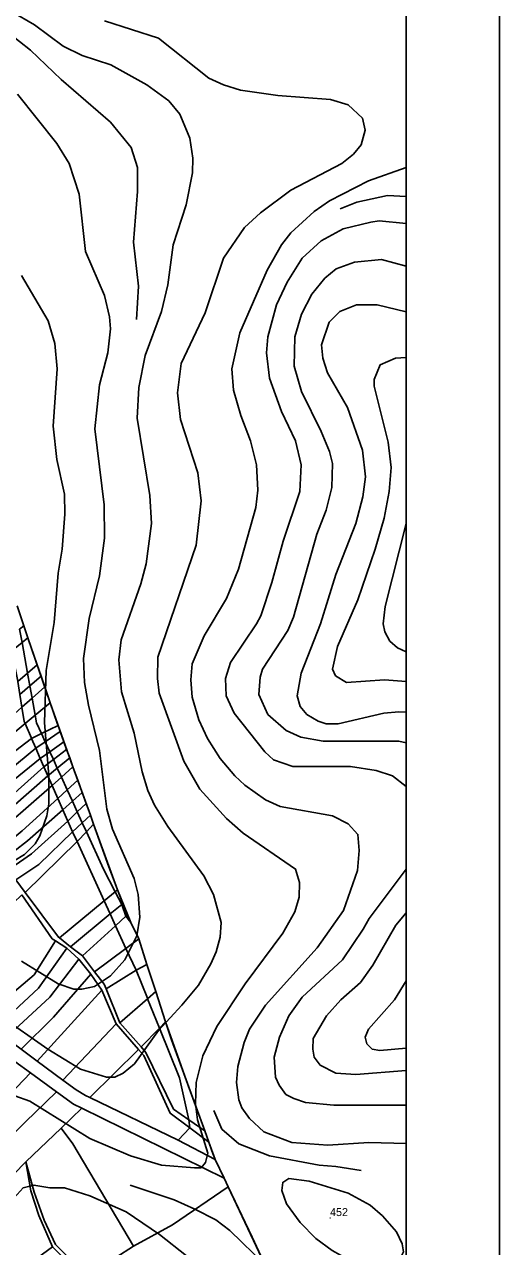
# Model space of a CAD drawing. Extents: x -510989 to -501240, y -1184665 to -1176089.
# Drawn here: x -508375 to -508019, y -1180002 to -1179086 of the extents above; entities that cross this region are included whole.
import ezdxf

# ---------------------------------------------------------------- set-up
doc = ezdxf.new("R2010")
doc.units = 0
for name, color, linetype in [('lesni_pozemek', 7, 'Continuous'), ('ostatni_plocha_x_ostatni_komunikace', 7, 'Continuous'), ('ostatni_plocha_x_silnice', 7, 'Continuous'), ('popis', 7, 'Continuous'), ('rozpiska', 7, 'Continuous'), ('vodni_plocha_x_vodni_tok_v_koryt_prir_n_upr', 7, 'Continuous'), ('vrstevnice_01', 7, 'Continuous'), ('vrstevnice_02', 7, 'Continuous'), ('vrstevnice_03', 7, 'Continuous'), ('vrstevnice_05', 7, 'Continuous')]:
    doc.layers.add(name, color=color, linetype=linetype)

msp = doc.modelspace()

# ---------------------------------------------------------------- linework, layer by layer
at = {"layer": 'lesni_pozemek'}
for points in [[(-508375.28, -1179536.65), (-508372.26, -1179545.49), (-508376.69, -1179549.11), (-508378.49, -1179539.21)], [(-508372.26, -1179545.49), (-508365.32, -1179565.8), (-508372.54, -1179571.99), (-508376.69, -1179549.11)], [(-508365.32, -1179565.8), (-508362.35, -1179574.47), (-508370.78, -1179581.68), (-508372.54, -1179571.99)], [(-508362.35, -1179574.47), (-508359.69, -1179582.26), (-508369.13, -1179590.78), (-508370.78, -1179581.68)], [(-508359.69, -1179582.26), (-508355.58, -1179594.3), (-508366.8, -1179603.6), (-508369.13, -1179590.78)], [(-508355.58, -1179594.3), (-508350.34, -1179609.63), (-508349.73, -1179611.32), (-508362.08, -1179617.47), (-508365.74, -1179609.44), (-508366.8, -1179603.6)], [(-508375.12, -1179608.36), (-508374.43, -1179609.93), (-508432.44, -1179658), (-508439.11, -1179650.99), (-508407.25, -1179625.19), (-508376.81, -1179597.71)], [(-508369.63, -1179620.89), (-508369.51, -1179621.18), (-508426.38, -1179664.36), (-508432.44, -1179658), (-508374.43, -1179609.93)], [(-508348.08, -1179615.91), (-508359.29, -1179623.59), (-508362.08, -1179617.47), (-508349.73, -1179611.32)], [(-508366.34, -1179628.42), (-508399.73, -1179655.76), (-508422.61, -1179671.19), (-508426.38, -1179664.36), (-508369.51, -1179621.18)], [(-508345.34, -1179623.5), (-508355.9, -1179631.02), (-508359.29, -1179623.59), (-508348.08, -1179615.91)], [(-508343.27, -1179629.27), (-508353.2, -1179636.93), (-508355.9, -1179631.02), (-508345.34, -1179623.5)], [(-508362.99, -1179636.07), (-508397.99, -1179664.33), (-508419.67, -1179678.67), (-508422.61, -1179671.19), (-508399.73, -1179655.76), (-508366.34, -1179628.42)], [(-508340.96, -1179635.68), (-508350.27, -1179643.36), (-508353.2, -1179636.93), (-508343.27, -1179629.27)], [(-508360.24, -1179642.36), (-508394.41, -1179672.71), (-508414.98, -1179684.95), (-508419.35, -1179679.5), (-508419.67, -1179678.67), (-508397.99, -1179664.33), (-508362.99, -1179636.07)], [(-508357.27, -1179649.13), (-508383.88, -1179672.33), (-508409.65, -1179691.6), (-508414.98, -1179684.95), (-508394.41, -1179672.71), (-508360.24, -1179642.36)], [(-508338.55, -1179642.35), (-508347.16, -1179650.18), (-508350.27, -1179643.36), (-508340.96, -1179635.68)], [(-508338.55, -1179642.35), (-508334.94, -1179652.39), (-508342.85, -1179659.62), (-508347.16, -1179650.18)], [(-508354.06, -1179656.46), (-508403.49, -1179699.29), (-508409.65, -1179691.6), (-508383.88, -1179672.33), (-508357.27, -1179649.13)], [(-508349.87, -1179666.04), (-508376.53, -1179690.45), (-508397.66, -1179707.63), (-508403.49, -1179699.29), (-508354.06, -1179656.46)], [(-508334.94, -1179652.39), (-508331.63, -1179661.58), (-508338.93, -1179668.21), (-508342.85, -1179659.62)], [(-508346.08, -1179674.71), (-508372.64, -1179697.96), (-508393.3, -1179713.87), (-508397.66, -1179707.63), (-508376.53, -1179690.45), (-508349.87, -1179666.04)], [(-508331.63, -1179661.58), (-508328.66, -1179669.81), (-508335.3, -1179676.16), (-508338.93, -1179668.21)], [(-508328.66, -1179669.81), (-508325.46, -1179678.69), (-508331.57, -1179684.33), (-508335.3, -1179676.16)], [(-508342.64, -1179682.55), (-508342.44, -1179683), (-508369.66, -1179707.55), (-508387.54, -1179720.12), (-508393.3, -1179713.87), (-508372.64, -1179697.96), (-508346.08, -1179674.71)], [(-508325.46, -1179678.69), (-508323.04, -1179685.4), (-508328.5, -1179691.06), (-508331.57, -1179684.33)], [(-508338.81, -1179691), (-508364.15, -1179715.53), (-508381.36, -1179727), (-508381.97, -1179726.17), (-508387.54, -1179720.12), (-508369.66, -1179707.55), (-508342.44, -1179683)], [(-508323.04, -1179685.4), (-508311.57, -1179717.24), (-508307.73, -1179727.9), (-508305.17, -1179734.59), (-508306.93, -1179736.06), (-508315.72, -1179719.07), (-508328.5, -1179691.06)], [(-508335.49, -1179698.31), (-508374.33, -1179736.49), (-508381.36, -1179727), (-508364.15, -1179715.53), (-508338.81, -1179691)], [(-508335.49, -1179698.31), (-508315.24, -1179742.94), (-508348.72, -1179770.69), (-508349.45, -1179770.12), (-508374.33, -1179736.49)], [(-508306.93, -1179736.06), (-508305.17, -1179734.59), (-508301.26, -1179744.83), (-508302.06, -1179745.49)], [(-508376.78, -1179738.27), (-508354.07, -1179771.31), (-508351.52, -1179772.94), (-508367.55, -1179798.25), (-508407.24, -1179831.91), (-508438.55, -1179808.7), (-508445.83, -1179804.3)], [(-508310.75, -1179752.69), (-508340.36, -1179777.21), (-508348.72, -1179770.69), (-508315.24, -1179742.94)], [(-508306.69, -1179761.51), (-508331.42, -1179784.18), (-508340.36, -1179777.21), (-508310.75, -1179752.69)], [(-508302.06, -1179745.49), (-508301.26, -1179744.83), (-508301.01, -1179745.49), (-508300.82, -1179745.98), (-508300.48, -1179746.87), (-508298.23, -1179752.78), (-508298.86, -1179754.33)], [(-508298.86, -1179754.33), (-508298.23, -1179752.78), (-508297.34, -1179754.61), (-508296.57, -1179756.18), (-508295.18, -1179759.04)], [(-508298.83, -1179778.58), (-508322.34, -1179796.08), (-508331.42, -1179784.18), (-508306.69, -1179761.51)], [(-508351.52, -1179772.94), (-508343.01, -1179778.39), (-508364.37, -1179808.2), (-508397.48, -1179839.14), (-508407.24, -1179831.91), (-508367.55, -1179798.25)], [(-508343.01, -1179778.39), (-508334.12, -1179786.6), (-508355.81, -1179815.14), (-508388.85, -1179845.53), (-508397.48, -1179839.14), (-508364.37, -1179808.2)], [(-508291.31, -1179794.91), (-508313.8, -1179808.92), (-508315.24, -1179805.39), (-508322.34, -1179796.08), (-508298.83, -1179778.58)], [(-508334.12, -1179786.6), (-508325.1, -1179797.79), (-508353.02, -1179830.13), (-508377.34, -1179854.07), (-508388.85, -1179845.53), (-508355.81, -1179815.14)], [(-508325.1, -1179797.79), (-508317.01, -1179809.73), (-508365.34, -1179862.96), (-508377.34, -1179854.07), (-508353.02, -1179830.13)], [(-508291.31, -1179794.91), (-508282.83, -1179815.88), (-508282.69, -1179816.22), (-508303.46, -1179834.36), (-508313.8, -1179808.92)], [(-508317.01, -1179809.73), (-508306.28, -1179834.94), (-508346.11, -1179877.21), (-508365.34, -1179862.96)], [(-508282.69, -1179816.22), (-508273.74, -1179838.34), (-508287.58, -1179852.38), (-508303.46, -1179834.36)], [(-508306.28, -1179834.94), (-508289.48, -1179854.27), (-508325.79, -1179890.38), (-508329.1, -1179888.78), (-508336.21, -1179884.55), (-508346.11, -1179877.21)], [(-508273.74, -1179838.34), (-508258.72, -1179875.46), (-508251.76, -1179906.97), (-508263.28, -1179899.04), (-508283.99, -1179856.46), (-508287.58, -1179852.38)], [(-508289.48, -1179854.27), (-508285.58, -1179858.75), (-508265.71, -1179902.1), (-508251.05, -1179913.07), (-508259.65, -1179922.4), (-508325.79, -1179890.38)], [(-508370.42, -1179871.92), (-508401.61, -1179904.42), (-508458.1, -1179958.48), (-508498.54, -1179988.71), (-508501.52, -1179976.96), (-508501.92, -1179965.5), (-508470.77, -1179943.05), (-508410.19, -1179889.28), (-508382.16, -1179863.41)], [(-508350.98, -1179886.01), (-508374.4, -1179908.75), (-508410.81, -1179945.25), (-508441.23, -1179972.85), (-508490.99, -1180012.47), (-508498.54, -1179988.71), (-508458.1, -1179958.48), (-508401.61, -1179904.42), (-508370.42, -1179871.92)], [(-508338.03, -1179895.39), (-508331.91, -1179898.4), (-508347.37, -1179913.24), (-508373.72, -1179938.52), (-508401.29, -1179966.61), (-508438.7, -1179998.77), (-508483.59, -1180035.75), (-508490.99, -1180012.47), (-508441.23, -1179972.85), (-508410.81, -1179945.25), (-508374.4, -1179908.75), (-508350.98, -1179886.01)], [(-508347.37, -1179913.24), (-508331.91, -1179898.4), (-508225.42, -1179950.88), (-508222.42, -1179957.19), (-508264.07, -1179985.88), (-508293.14, -1180001.85), (-508338.56, -1179924.99)], [(-508338.56, -1179924.99), (-508293.14, -1180001.85), (-508306.41, -1180010.22), (-508325.34, -1180026.8), (-508351.58, -1180000.65), (-508360.15, -1179982.23), (-508367.63, -1179961.39), (-508373.72, -1179938.52), (-508347.37, -1179913.24)], [(-508370.14, -1179960.34), (-508364.19, -1179978.89), (-508353.93, -1180002.31), (-508373.58, -1180016.68), (-508396.42, -1180036.4), (-508416.63, -1180051.92), (-508475.36, -1180090.66), (-508483.59, -1180035.75), (-508438.7, -1179998.77), (-508401.29, -1179966.61), (-508373.72, -1179938.52)], [(-508264.07, -1179985.88), (-508222.42, -1179957.19), (-508204.32, -1179995.16), (-508177.34, -1180053.09), (-508152.46, -1180106.83), (-508173.6, -1180123.17), (-508192.01, -1180134.69), (-508215.78, -1180151.38), (-508240.41, -1180170.53), (-508260.19, -1180138.45), (-508277.13, -1180118.72), (-508286.73, -1180111.41), (-508303.87, -1180065.86), (-508325.34, -1180026.8), (-508306.41, -1180010.22), (-508293.14, -1180001.85)]]:
    msp.add_lwpolyline(points, close=True, dxfattribs=at)
at = {"layer": 'ostatni_plocha_x_ostatni_komunikace'}
for points in [[(-508376.69, -1179549.11), (-508372.54, -1179571.99), (-508379.9, -1179578.29), (-508380.14, -1179576.77), (-508384.32, -1179555.34)], [(-508372.54, -1179571.99), (-508370.78, -1179581.68), (-508378.33, -1179588.14), (-508379.9, -1179578.29)], [(-508370.78, -1179581.68), (-508369.13, -1179590.78), (-508376.81, -1179597.71), (-508378.33, -1179588.14)], [(-508369.13, -1179590.78), (-508366.8, -1179603.6), (-508374.43, -1179609.93), (-508375.12, -1179608.36), (-508376.81, -1179597.71)], [(-508365.74, -1179609.44), (-508362.08, -1179617.47), (-508369.51, -1179621.18), (-508369.63, -1179620.89), (-508374.43, -1179609.93), (-508366.8, -1179603.6)], [(-508362.08, -1179617.47), (-508359.29, -1179623.59), (-508366.34, -1179628.42), (-508369.51, -1179621.18)], [(-508359.29, -1179623.59), (-508355.9, -1179631.02), (-508362.99, -1179636.07), (-508366.34, -1179628.42)], [(-508355.9, -1179631.02), (-508353.2, -1179636.93), (-508360.24, -1179642.36), (-508362.99, -1179636.07)], [(-508353.2, -1179636.93), (-508350.27, -1179643.36), (-508357.27, -1179649.13), (-508360.24, -1179642.36)], [(-508350.27, -1179643.36), (-508347.16, -1179650.18), (-508354.06, -1179656.46), (-508357.27, -1179649.13)], [(-508347.16, -1179650.18), (-508342.85, -1179659.62), (-508349.87, -1179666.04), (-508354.06, -1179656.46)], [(-508342.85, -1179659.62), (-508338.93, -1179668.21), (-508346.08, -1179674.71), (-508349.87, -1179666.04)], [(-508338.93, -1179668.21), (-508335.3, -1179676.16), (-508342.44, -1179683), (-508342.64, -1179682.55), (-508346.08, -1179674.71)], [(-508335.3, -1179676.16), (-508331.57, -1179684.33), (-508338.81, -1179691), (-508342.44, -1179683)], [(-508331.57, -1179684.33), (-508328.5, -1179691.06), (-508335.49, -1179698.31), (-508338.81, -1179691)], [(-508328.5, -1179691.06), (-508315.72, -1179719.07), (-508306.93, -1179736.06), (-508315.24, -1179742.94), (-508335.49, -1179698.31)], [(-508315.24, -1179742.94), (-508306.93, -1179736.06), (-508302.06, -1179745.49), (-508310.75, -1179752.69)], [(-508302.06, -1179745.49), (-508298.86, -1179754.33), (-508306.69, -1179761.51), (-508310.75, -1179752.69)], [(-508298.86, -1179754.33), (-508295.18, -1179759.04), (-508289.71, -1179770.24), (-508289.15, -1179771.38), (-508298.83, -1179778.58), (-508306.69, -1179761.51)], [(-508289.15, -1179771.38), (-508283.14, -1179790.49), (-508291.31, -1179794.91), (-508298.83, -1179778.58)], [(-508291.31, -1179794.91), (-508283.14, -1179790.49), (-508276.53, -1179810.83), (-508282.69, -1179816.22), (-508282.83, -1179815.88)], [(-508276.53, -1179810.83), (-508269.12, -1179833.65), (-508273.74, -1179838.34), (-508282.69, -1179816.22)], [(-508269.12, -1179833.65), (-508264.73, -1179847.18), (-508239.71, -1179915.27), (-508251.76, -1179906.97), (-508258.72, -1179875.46), (-508273.74, -1179838.34)], [(-508251.05, -1179913.07), (-508251.76, -1179906.97), (-508239.71, -1179915.27), (-508236.74, -1179923.78)], [(-508259.65, -1179922.4), (-508251.05, -1179913.07), (-508236.74, -1179923.78), (-508234.45, -1179930.36), (-508231.98, -1179936.72)]]:
    msp.add_lwpolyline(points, close=True, dxfattribs=at)
msp.add_lwpolyline([(-508381.36, -1179727), (-508374.33, -1179736.49), (-508349.45, -1179770.12), (-508348.72, -1179770.69), (-508340.36, -1179777.21), (-508331.42, -1179784.18), (-508322.34, -1179796.08), (-508315.24, -1179805.39), (-508313.8, -1179808.92), (-508303.46, -1179834.36), (-508287.58, -1179852.38), (-508283.99, -1179856.46), (-508263.28, -1179899.04), (-508251.76, -1179906.97), (-508251.05, -1179913.07), (-508265.71, -1179902.1), (-508285.58, -1179858.75), (-508289.48, -1179854.27), (-508306.28, -1179834.94), (-508317.01, -1179809.73), (-508325.1, -1179797.79), (-508334.12, -1179786.6), (-508343.01, -1179778.39), (-508351.52, -1179772.94), (-508354.07, -1179771.31), (-508376.78, -1179738.27)], dxfattribs=at)
at = {"layer": 'ostatni_plocha_x_silnice'}
msp.add_lwpolyline([(-508377.34, -1179854.07), (-508365.34, -1179862.96), (-508346.11, -1179877.21), (-508336.21, -1179884.55), (-508329.1, -1179888.78), (-508325.79, -1179890.38), (-508259.65, -1179922.4), (-508231.98, -1179936.72), (-508225.42, -1179950.88), (-508331.91, -1179898.4), (-508338.03, -1179895.39), (-508350.98, -1179886.01), (-508370.42, -1179871.92), (-508382.16, -1179863.41)], dxfattribs=at)
at = {"layer": 'popis'}
msp.add_lwpolyline([(-508380.42, -1179521.72), (-508372.26, -1179545.49), (-508355.58, -1179594.3), (-508338.55, -1179642.35), (-508325.46, -1179678.69), (-508323.04, -1179685.4), (-508305.17, -1179734.59), (-508295.18, -1179759.04), (-508289.15, -1179771.38), (-508283.14, -1179790.49), (-508276.53, -1179810.83), (-508269.12, -1179833.65), (-508252.22, -1179881.23), (-508239.71, -1179915.27), (-508236.74, -1179923.78), (-508231.98, -1179936.72), (-508225.42, -1179950.88), (-508222.42, -1179957.19), (-508190.83, -1180024.12)], dxfattribs=at)
at = {"layer": 'rozpiska'}
for points in [[(-508019.09, -1176098), (-508019.09, -1184498), (-510989.09, -1184498), (-510989.09, -1176098)], [(-508089.09, -1176168), (-508089.09, -1184428), (-510919.09, -1184428), (-510919.09, -1176168)]]:
    msp.add_lwpolyline(points, close=True, dxfattribs=at)
at = {"layer": 'vodni_plocha_x_vodni_tok_v_koryt_prir_n_upr'}
msp.add_lwpolyline([(-508370.14, -1179960.34), (-508373.72, -1179938.52), (-508367.63, -1179961.39), (-508360.15, -1179982.23), (-508351.58, -1180000.65), (-508325.34, -1180026.8), (-508303.87, -1180065.86), (-508286.73, -1180111.41), (-508277.13, -1180118.72), (-508260.19, -1180138.45), (-508240.41, -1180170.53), (-508241.39, -1180171.23), (-508243.46, -1180173.21), (-508260.33, -1180143.53), (-508277.13, -1180123.03), (-508288.99, -1180112.76), (-508305.92, -1180067.56), (-508326.79, -1180029.11), (-508353.93, -1180002.31), (-508364.19, -1179978.89)], close=True, dxfattribs=at)
at = {"layer": 'vrstevnice_01'}
for points in [[(-508382.19, -1179889), (-508370.91, -1179893), (-508326, -1179921), (-508295.41, -1179934), (-508272.31, -1179941), (-508247.5, -1179943), (-508242.59, -1179943), (-508239.19, -1179939), (-508237.59, -1179932), (-508245.31, -1179907), (-508246.69, -1179895), (-508246.19, -1179879), (-508241.19, -1179859), (-508230.91, -1179837), (-508209.59, -1179805), (-508181.31, -1179767), (-508172.31, -1179751), (-508169.19, -1179740), (-508169, -1179729), (-508172, -1179719), (-508211.09, -1179692), (-508223.5, -1179681), (-508243.59, -1179659), (-508255.59, -1179638), (-508273.91, -1179587), (-508275.19, -1179576), (-508274.91, -1179560), (-508246.31, -1179476), (-508242.59, -1179443), (-508244.91, -1179422), (-508257.91, -1179382), (-508260.19, -1179362), (-508257.5, -1179340), (-508239.5, -1179302), (-508225.81, -1179261), (-508210.09, -1179238), (-508198.09, -1179227), (-508175.31, -1179210), (-508137.31, -1179190), (-508128.5, -1179183), (-508122.69, -1179176), (-508119.59, -1179165), (-508121.59, -1179156), (-508132.5, -1179146), (-508145.69, -1179142), (-508185, -1179139), (-508213.09, -1179135), (-508225.91, -1179131), (-508236.91, -1179126), (-508274.41, -1179096), (-508314.91, -1179083)], [(-508377, -1179788), (-508349.69, -1179805), (-508337.81, -1179809), (-508331.81, -1179809), (-508322.5, -1179807), (-508310.5, -1179799), (-508299.81, -1179787), (-508290.69, -1179769), (-508288.41, -1179755), (-508289.81, -1179738), (-508292.81, -1179726), (-508309, -1179689), (-508313.19, -1179674), (-508318.69, -1179630), (-508326.81, -1179596), (-508329.81, -1179579), (-508330.59, -1179561), (-508326.41, -1179531), (-508318.59, -1179499), (-508315, -1179471), (-508315.09, -1179446), (-508322.09, -1179389), (-508318.59, -1179356), (-508312.5, -1179332), (-508310.31, -1179314), (-508311.09, -1179305), (-508315, -1179289), (-508329.19, -1179256), (-508333.81, -1179213), (-508341.5, -1179190), (-508350.5, -1179175), (-508380.09, -1179138)], [(-508089.09, -1179234.93), (-508109.31, -1179233), (-508115.41, -1179234), (-508136.19, -1179239), (-508152.59, -1179248), (-508166.81, -1179261), (-508178.19, -1179279), (-508186.19, -1179296), (-508192.69, -1179320), (-508193.69, -1179332), (-508191.41, -1179351), (-508182.41, -1179376), (-508171.91, -1179398), (-508167.59, -1179416), (-508168.69, -1179436), (-508181.09, -1179473), (-508189.5, -1179504), (-508197.81, -1179529), (-508201.19, -1179535), (-508220.5, -1179564), (-508224.31, -1179576), (-508223.81, -1179589), (-508217.91, -1179602), (-508194.81, -1179631), (-508188.41, -1179637), (-508173.91, -1179642), (-508130.81, -1179642), (-508111.5, -1179645), (-508099.19, -1179649), (-508089.09, -1179657.17)], [(-508089.09, -1179601.33), (-508094.5, -1179601), (-508105.69, -1179602), (-508139.81, -1179610), (-508148.91, -1179610), (-508154.91, -1179608), (-508163.31, -1179603), (-508168.41, -1179597), (-508170.59, -1179589), (-508167.69, -1179572), (-508153.19, -1179535), (-508141.59, -1179498), (-508126.81, -1179460), (-508121.5, -1179440), (-508119.41, -1179425), (-508121.59, -1179405), (-508133, -1179373), (-508148, -1179347), (-508151.41, -1179336), (-508152.31, -1179326), (-508146.69, -1179309), (-508138.69, -1179301), (-508126.09, -1179296), (-508110.81, -1179296), (-508089.09, -1179301.15)], [(-508089.09, -1179459.98), (-508089.09, -1179460), (-508104.81, -1179522), (-508106.31, -1179535), (-508105, -1179541), (-508101.31, -1179548), (-508095.59, -1179553), (-508089.09, -1179556.16)], [(-508089.09, -1179719.04), (-508116.81, -1179756), (-508121.31, -1179764), (-508136.81, -1179787), (-508167, -1179815), (-508177, -1179829), (-508183.91, -1179845), (-508187.91, -1179860), (-508186.81, -1179875), (-508184.09, -1179881), (-508179, -1179888), (-508173.19, -1179891), (-508164.31, -1179894), (-508143.19, -1179896), (-508089.09, -1179896)], [(-508089.09, -1179853.25), (-508108.69, -1179855), (-508114.5, -1179854), (-508118.41, -1179850), (-508119.81, -1179845), (-508117.31, -1179839), (-508097.69, -1179817), (-508089.09, -1179802.78)], [(-508106.81, -1179979), (-508096.19, -1179991), (-508091.91, -1180000), (-508091.09, -1180006), (-508093, -1180010), (-508099.81, -1180016), (-508105, -1180017), (-508119.81, -1180016), (-508131.91, -1180012), (-508144.31, -1180005), (-508156.59, -1179996), (-508168.31, -1179984), (-508178.69, -1179970), (-508182.19, -1179960), (-508181.41, -1179954), (-508176.81, -1179951), (-508161.59, -1179953), (-508132.5, -1179962), (-508116, -1179971), (-508106.81, -1179979)]]:
    msp.add_lwpolyline(points, dxfattribs=at)
at = {"layer": 'vrstevnice_02'}
for points in [[(-508384.69, -1179076), (-508367.31, -1179086), (-508345.81, -1179102), (-508331.69, -1179109), (-508310.19, -1179116), (-508283.19, -1179131), (-508266.81, -1179143), (-508258.41, -1179153), (-508251, -1179171), (-508248.81, -1179186), (-508249.09, -1179197), (-508253.81, -1179221), (-508263.59, -1179251), (-508267.41, -1179281), (-508272.31, -1179301), (-508284.41, -1179334), (-508289.31, -1179358), (-508290.41, -1179381), (-508281, -1179439), (-508279.69, -1179460), (-508283.69, -1179490), (-508287.69, -1179505), (-508302.5, -1179547), (-508304.19, -1179562), (-508302.19, -1179586), (-508292.69, -1179617), (-508286.81, -1179646), (-508282.5, -1179660), (-508277.41, -1179671), (-508267.59, -1179687), (-508240.59, -1179724), (-508233.19, -1179738), (-508227.59, -1179759), (-508228.41, -1179770), (-508231.41, -1179781), (-508235.19, -1179790), (-508244.5, -1179806), (-508257, -1179821), (-508274.5, -1179840), (-508292.5, -1179865), (-508301, -1179872), (-508307.31, -1179875), (-508313.41, -1179875), (-508332.91, -1179869), (-508357.31, -1179854), (-508393.31, -1179829)], [(-508089.09, -1179924.71), (-508117.09, -1179924), (-508147.69, -1179926), (-508174.69, -1179924), (-508195.5, -1179916), (-508206.41, -1179906), (-508212, -1179898), (-508214.31, -1179892), (-508216.09, -1179879), (-508215.09, -1179867), (-508210.31, -1179849), (-508206.31, -1179839), (-508194.31, -1179821), (-508155.59, -1179778), (-508136, -1179750), (-508125.5, -1179720), (-508124.31, -1179705), (-508125.19, -1179693), (-508132.5, -1179685), (-508144.19, -1179679), (-508183.41, -1179672), (-508194.31, -1179667), (-508209.81, -1179656), (-508217.31, -1179649), (-508228.41, -1179636), (-508237.81, -1179621), (-508244.19, -1179607), (-508249.19, -1179590), (-508250.19, -1179577), (-508249.31, -1179565), (-508240.19, -1179544), (-508223.5, -1179516), (-508214.5, -1179494), (-508201.69, -1179448), (-508200, -1179435), (-508201.09, -1179416), (-508205.59, -1179398), (-508212.81, -1179379), (-508218.31, -1179360), (-508219.59, -1179344), (-508213.69, -1179317), (-508193.19, -1179270), (-508182.41, -1179251), (-508175.5, -1179242), (-508157.81, -1179226), (-508146.31, -1179218), (-508117.19, -1179203), (-508089.09, -1179192.83)], [(-508089.09, -1179624.23), (-508094.5, -1179623), (-508151.19, -1179623), (-508167.91, -1179620), (-508178.81, -1179615), (-508192.5, -1179603), (-508199.41, -1179588), (-508198.31, -1179575), (-508196.59, -1179569), (-508177.69, -1179540), (-508173.41, -1179530), (-508155.81, -1179468), (-508148.91, -1179450), (-508144.59, -1179433), (-508144.19, -1179415), (-508146.41, -1179406), (-508152.69, -1179391), (-508167.41, -1179361), (-508173, -1179342), (-508172.41, -1179320), (-508167.41, -1179303), (-508159.69, -1179288), (-508149.81, -1179276), (-508141.41, -1179269), (-508127.69, -1179264), (-508107.59, -1179262), (-508089.09, -1179267)], [(-508377.09, -1179274), (-508357, -1179308), (-508352.09, -1179325), (-508350.41, -1179344), (-508353.31, -1179387), (-508350.59, -1179412), (-508345, -1179438), (-508344.59, -1179453), (-508346.69, -1179479), (-508349.69, -1179497), (-508352.69, -1179534), (-508358.59, -1179570), (-508359.81, -1179609), (-508356.5, -1179649), (-508356.69, -1179670), (-508358.09, -1179679), (-508363.31, -1179694), (-508366.81, -1179700), (-508374.81, -1179708), (-508383, -1179713)], [(-508089.09, -1179335.49), (-508096.91, -1179336), (-508108.5, -1179341), (-508113.09, -1179352), (-508113.09, -1179357), (-508102.5, -1179399), (-508100.31, -1179418), (-508101.81, -1179436), (-508105.41, -1179456), (-508112.19, -1179479), (-508125.09, -1179517), (-508140.41, -1179552), (-508144.09, -1179569), (-508142, -1179574), (-508133.59, -1179579), (-508105.19, -1179577), (-508089.09, -1179578.42)], [(-508089.09, -1179870.15), (-508126.81, -1179873), (-508141.69, -1179872), (-508153.41, -1179866), (-508157.81, -1179860), (-508159, -1179854), (-508158.59, -1179846), (-508148.59, -1179829), (-508137.81, -1179817), (-508123.09, -1179804), (-508114, -1179791), (-508096.69, -1179761), (-508089.09, -1179751.88)], [(-508397.69, -1180014), (-508395.81, -1179995), (-508393.19, -1179984), (-508384.91, -1179968), (-508375.91, -1179958), (-508367.81, -1179956), (-508355.91, -1179958), (-508344.81, -1179958), (-508325.81, -1179964), (-508298.59, -1179976), (-508273.69, -1179993), (-508213, -1180041)]]:
    msp.add_lwpolyline(points, dxfattribs=at)
at = {"layer": 'vrstevnice_03'}
for points in [[(-508396.81, -1179087), (-508386.81, -1179092), (-508370.31, -1179105), (-508347.31, -1179127), (-508310.31, -1179159), (-508294.91, -1179178), (-508290.31, -1179193), (-508290.31, -1179211), (-508293.31, -1179249), (-508289.5, -1179282), (-508291, -1179307)], [(-508089.09, -1179214.76), (-508102.91, -1179214), (-508126, -1179219), (-508138.41, -1179224)], [(-508233, -1179900), (-508227, -1179914), (-508214.31, -1179925), (-508191.31, -1179934), (-508154.19, -1179941), (-508141.59, -1179942), (-508122.59, -1179945)], [(-508136.41, -1180046), (-508154.69, -1180040), (-508176.91, -1180030), (-508194.31, -1180016), (-508221.09, -1179990), (-508231.59, -1179982), (-508247.19, -1179974), (-508262.81, -1179967), (-508295.81, -1179956)]]:
    msp.add_lwpolyline(points, dxfattribs=at)

# ---------------------------------------------------------------- texts
at = {"layer": 'vrstevnice_05'}
for s, p in [('452', (-508145.99, -1179979.22)), ('.', (-508146.99, -1179981.12))]:
    msp.add_text(s, height=6, dxfattribs=at).set_placement(p)

doc.saveas('drawing.dxf')
